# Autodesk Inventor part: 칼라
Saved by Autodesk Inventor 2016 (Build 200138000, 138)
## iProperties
Created: 2024-08
Part Number: 칼라
Material: 일반
Document SubType Name: Modeling
Designer: pc-2
Density: 1 g/cm^3
Appearance: 기본값
Author: jhkim
Sending System: Autodesk Inventor 2025
Preprocessor: ST-DEVELOPER v20
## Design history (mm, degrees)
node "칼라1"
node "솔리드2"
node "솔리드1"
